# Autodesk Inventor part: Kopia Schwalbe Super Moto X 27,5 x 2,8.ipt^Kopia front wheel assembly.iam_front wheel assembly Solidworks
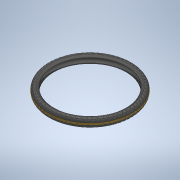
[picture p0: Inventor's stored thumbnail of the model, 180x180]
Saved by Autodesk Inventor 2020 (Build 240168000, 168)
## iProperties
Created: 2017-09
Part Number: Kopia Schwalbe Super Moto X 27,5 x 2,8.ipt^Kopia front wheel assembly.iam_front wheel assembly Solidworks
Material: solidworks materials|BUTYL|223
Document SubType Name: Modeling
Designer: Tomasz
Density: 1.1592 g/cm^3
Appearance: 76,76,76
Sending System: SolidWorks 2017
Last Author: Tomasz
Last Saved: 2017-11-20
Author: Tomasz
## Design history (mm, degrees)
feature "Schwalbe Super Moto X 27,5 x 2,8.ipt"
sketch "Esquisse1"
  geometry: C1 r 310.569 at (0, -293.4) reference; C2 r 343.288 at (0, -293.4); 1 further point
  constraints: 1 centre point, 1 coincident
feature "SrfExtrusion1" sketch "Esquisse1" dims "d0" = 10, "d1" = 0
node "Bryła1"
body "Srf1"
